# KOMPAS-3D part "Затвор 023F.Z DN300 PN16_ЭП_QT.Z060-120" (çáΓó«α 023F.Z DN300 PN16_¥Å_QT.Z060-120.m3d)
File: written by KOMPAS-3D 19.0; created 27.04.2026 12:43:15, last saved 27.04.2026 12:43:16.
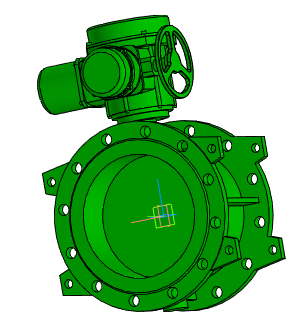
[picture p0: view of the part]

Document properties: Полное имя файла: Затвор 023F.Z DN300 PN16 + электропривод QT.Z060-120.a3d

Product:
- Part/product: Затвор 023F.Z DN300 PN16_ЭП_QT.Z060-120
    Масса: 154.797
  - Body: Тело 1
      Масса: 155.099

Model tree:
1. Операция без истории:1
